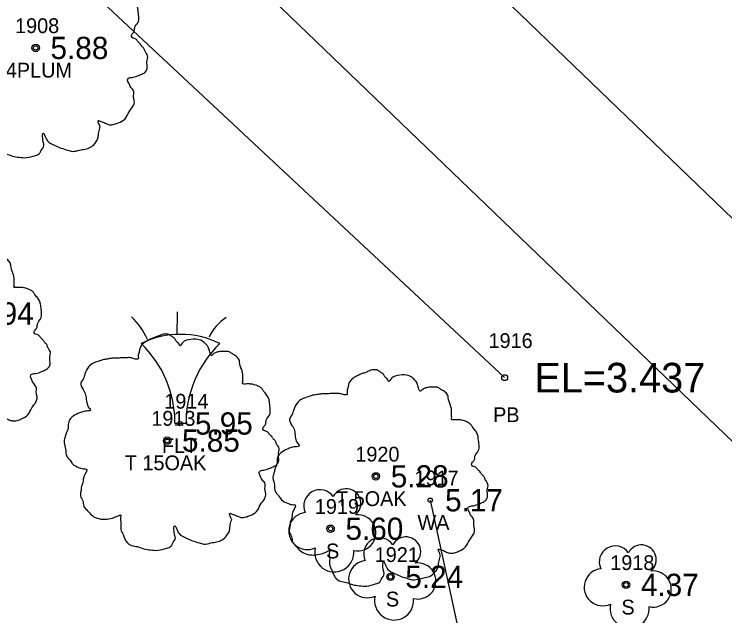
# Model space of a CAD drawing. Extents: x 2608598 to 2610682, y 641451 to 643526.
# Drawn here: x 2609231.28 to 2609279.19, y 642898.29 to 642938.88 of the extents above; entities that cross this region are included whole.
import ezdxf

# ---------------------------------------------------------------- set-up
doc = ezdxf.new("R2010")
doc.units = 0
for name, color, linetype in [('RD_EX_BldgApp', 7, 'Continuous'), ('RD_EX_BldgApp_txCode', 7, 'Continuous'), ('RD_EX_DR_Pipe', 7, 'Continuous'), ('RD_EX_DR_Pipe_txCode', 7, 'Continuous'), ('RD_EX_Misc_txCode', 7, 'Continuous'), ('RD_EX_Road', 7, 'Continuous'), ('RD_EX_TX_BldgApp_ELEV', 7, 'Continuous'), ('RD_EX_TX_Misc_ELEV', 7, 'Continuous'), ('RD_EX_TX_VEG_ELEV', 7, 'Continuous'), ('RD_EX_VEG', 7, 'Continuous'), ('RD_EX_VEG_txCode', 7, 'Continuous'), ('RD_HC_Cl', 7, 'Continuous'), ('RD_SMD_Locator', 7, 'Continuous'), ('RD_TX_Pipe_ElevEX', 7, 'Continuous')]:
    doc.layers.add(name, color=color, linetype=linetype)

msp = doc.modelspace()

# ---------------------------------------------------------------- linework, layer by layer
at = {"layer": 'RD_EX_BldgApp'}
msp.add_line((2609242.116, 642911.284), (2609242.866, 642911.284), dxfattribs=at)
msp.add_lwpolyline([(2609259.329, 642906.089), (2609262.471, 642891.581), (2609238.117, 642881.572), (2609215.937, 642874.826), (2609203.404, 642873.665)], dxfattribs=at)
for centre, radius, start, end in [((2609204.409, 642918.622), 37.876, 358.0671, 0.2715), ((2609235.798, 642914.927), 4.895, 24.3279, 46.2665), ((2609247.379, 642915.678), 3.283, 123.2906, 154.4886), ((2609242.491, 642911.284), 5.997, 63.7794, 116.2206), ((2609234.616, 642911.284), 7.5, 0, 45.8366), ((2609250.366, 642911.284), 7.5, 134.1634, 180)]:
    msp.add_arc(centre, radius, start, end, dxfattribs=at)
at = {"layer": 'RD_EX_DR_Pipe'}
msp.add_lwpolyline([(2609067.894, 643101.844), (2609174.278, 642998.399), (2609174.637, 642998.15), (2609264.347, 642914.358)], dxfattribs=at)
at = {"layer": 'RD_EX_Road'}
msp.add_lwpolyline([(2608806.889, 643364.989), (2608810.184, 643361.1), (2608820.754, 643351.249), (2608881.81, 643292.235), (2608917.833, 643257.495), (2608933.208, 643242.709), (2608954.068, 643222.833), (2609026.064, 643154.189), (2609039.601, 643139.963), (2609073.879, 643106.954), (2609100.48, 643081.888), (2609124.194, 643058.866), (2609171.612, 643013.711), (2609183.195, 643002.284), (2609197.913, 642988.365), (2609247.586, 642940.954), (2609328.02, 642863.599), (2609402.609, 642790.299), (2609474.235, 642720.69), (2609483.838, 642711.579), (2609495.782, 642699.917), (2609509.808, 642686.45)], dxfattribs=at)
at = {"layer": 'RD_EX_VEG'}
for centre, radius in [((2609232.725, 642936.603), 0.25), ((2609232.712, 642936.585), 0.0001), ((2609241.588, 642910.111), 0.25), ((2609241.575, 642910.092), 0.0001), ((2609255.666, 642907.698), 0.25), ((2609255.653, 642907.679), 0.0001), ((2609252.612, 642904.167), 0.25), ((2609256.649, 642900.919), 0.25), ((2609272.529, 642900.378), 0.25)]:
    msp.add_circle(centre, radius, dxfattribs=at)
for centre, radius, start, end in [((2609251.891, 642905.714), 1.084, 34.9763, 204.756), ((2609253.657, 642905.869), 0.995, 308.7626, 152.0467), ((2609251.048, 642904.011), 1.257, 96.4518, 294.734), ((2609254.452, 642903.887), 1.218, 256.5667, 98.1046), ((2609255.928, 642902.466), 1.084, 34.9763, 204.756), ((2609257.695, 642902.621), 0.995, 308.7626, 152.0467), ((2609252.858, 642902.57), 1.318, 166.8827, 5.7589), ((2609271.808, 642901.925), 1.084, 34.9763, 204.756), ((2609273.574, 642902.08), 0.995, 308.7626, 152.0467), ((2609255.086, 642900.763), 1.257, 96.4518, 294.734), ((2609258.489, 642900.64), 1.218, 256.5667, 98.1046), ((2609270.965, 642900.222), 1.257, 96.4518, 294.734), ((2609274.368, 642900.099), 1.218, 256.5667, 98.1046), ((2609256.895, 642899.323), 1.318, 166.8827, 5.7589), ((2609272.774, 642898.782), 1.318, 166.8827, 5.7589)]:
    msp.add_arc(centre, radius, start, end, dxfattribs=at)
for points in [[(2609232.857, 642943.771), (2609232.557, 642943.796), (2609232.232, 642943.696), (2609231.982, 642943.596), (2609231.757, 642943.521), (2609231.532, 642943.421), (2609231.232, 642943.246), (2609231.008, 642943.046), (2609230.883, 642942.796), (2609230.833, 642942.571), (2609230.783, 642942.296), (2609230.783, 642942.121), (2609230.658, 642942.096), (2609230.508, 642942.121), (2609230.258, 642942.196), (2609230.008, 642942.196), (2609229.758, 642942.196), (2609229.408, 642942.171), (2609229.058, 642942.171), (2609228.784, 642942.121), (2609228.459, 642942.071), (2609228.084, 642941.946), (2609227.734, 642941.821), (2609227.434, 642941.572), (2609227.184, 642941.097), (2609227.059, 642940.747), (2609226.909, 642940.497), (2609227.059, 642940.047), (2609227.234, 642939.697), (2609227.259, 642939.497), (2609227.334, 642939.073), (2609227.434, 642938.848), (2609227.559, 642938.648), (2609227.484, 642938.623), (2609227.109, 642938.573), (2609226.809, 642938.473), (2609226.385, 642938.248), (2609226.16, 642938.023), (2609226.06, 642937.698), (2609226.035, 642937.348), (2609225.935, 642937.149), (2609225.86, 642936.874), (2609225.835, 642936.799), (2609225.785, 642936.474), (2609225.885, 642936.024), (2609225.91, 642935.674), (2609226.035, 642935.449), (2609226.185, 642935.274), (2609226.36, 642935.024), (2609226.759, 642934.8), (2609227.084, 642934.7), (2609227.284, 642934.675), (2609227.109, 642934.175), (2609227.059, 642933.825), (2609226.934, 642933.425), (2609226.934, 642933.35), (2609226.884, 642932.875), (2609227.034, 642932.55), (2609227.109, 642932.176), (2609227.284, 642931.951), (2609227.559, 642931.651), (2609227.884, 642931.426), (2609228.384, 642931.301), (2609228.784, 642931.326), (2609229.358, 642931.501), (2609229.608, 642931.576), (2609229.583, 642931.401), (2609229.608, 642931.026), (2609229.608, 642930.601), (2609229.758, 642930.277), (2609229.858, 642930.002), (2609230.008, 642929.752), (2609230.333, 642929.527), (2609230.733, 642929.452), (2609231.157, 642929.302), (2609231.607, 642929.227), (2609232.107, 642929.202), (2609232.707, 642929.352), (2609232.982, 642929.477), (2609233.082, 642929.652), (2609233.282, 642930.027), (2609233.232, 642930.252), (2609233.257, 642930.851), (2609233.356, 642930.676), (2609233.531, 642930.326), (2609234.031, 642930.027), (2609234.431, 642929.852), (2609234.906, 642929.702), (2609235.206, 642929.627), (2609235.68, 642929.702), (2609236.055, 642929.777), (2609236.43, 642929.902), (2609236.73, 642930.177), (2609236.905, 642930.451), (2609236.955, 642930.726), (2609237.03, 642931.101), (2609237.08, 642931.276)], [(2609237.08, 642931.276), (2609237.005, 642931.451), (2609236.955, 642931.701), (2609237.03, 642931.676), (2609237.205, 642931.626), (2609237.48, 642931.501), (2609237.705, 642931.426), (2609238.029, 642931.451), (2609238.304, 642931.551), (2609238.754, 642931.826), (2609239.029, 642932.301), (2609239.304, 642932.7), (2609239.379, 642933.025), (2609239.329, 642933.25), (2609239.304, 642933.75), (2609239.104, 642934), (2609239.054, 642934.125), (2609238.954, 642934.525), (2609239.029, 642934.575), (2609239.304, 642934.625), (2609239.679, 642934.75), (2609239.954, 642934.874), (2609240.179, 642935.049), (2609240.253, 642935.274), (2609240.229, 642935.674), (2609240.278, 642936.074), (2609240.204, 642936.224), (2609240.104, 642936.374), (2609240.029, 642936.574), (2609239.879, 642936.724), (2609239.779, 642936.874), (2609239.679, 642936.974), (2609239.554, 642937.124), (2609239.379, 642937.248), (2609239.229, 642937.298), (2609239.179, 642937.448), (2609239.329, 642937.648), (2609239.379, 642937.748), (2609239.404, 642937.973), (2609239.629, 642938.323), (2609239.679, 642938.723), (2609239.629, 642939.148), (2609239.579, 642939.423), (2609239.429, 642939.697), (2609239.229, 642939.947), (2609239.104, 642940.122), (2609238.929, 642940.247), (2609238.604, 642940.372), (2609238.354, 642940.422), (2609238.004, 642940.422), (2609237.805, 642940.472), (2609237.83, 642940.522), (2609237.83, 642940.672), (2609237.83, 642940.947), (2609237.755, 642941.397), (2609237.605, 642941.896), (2609237.605, 642941.921), (2609237.505, 642942.171), (2609237.28, 642942.371), (2609237.105, 642942.471), (2609236.905, 642942.596), (2609236.655, 642942.621), (2609236.355, 642942.621), (2609236.08, 642942.571), (2609235.88, 642942.471), (2609235.705, 642942.346), (2609235.63, 642942.496), (2609235.531, 642942.796), (2609235.481, 642942.946), (2609235.331, 642943.121), (2609235.106, 642943.321), (2609234.656, 642943.446), (2609234.031, 642943.371), (2609233.731, 642943.171), (2609233.581, 642942.996), (2609233.531, 642943.121), (2609233.331, 642943.321), (2609233.232, 642943.496), (2609233.057, 642943.621), (2609232.907, 642943.721), (2609232.807, 642943.771)], [(2609230.524, 642911.295), (2609230.449, 642911.47), (2609230.399, 642911.72), (2609230.474, 642911.695), (2609230.649, 642911.645), (2609230.924, 642911.52), (2609231.149, 642911.445), (2609231.473, 642911.47), (2609231.748, 642911.57), (2609232.198, 642911.845), (2609232.473, 642912.32), (2609232.748, 642912.72), (2609232.823, 642913.045), (2609232.773, 642913.27), (2609232.748, 642913.769), (2609232.548, 642914.019), (2609232.498, 642914.144), (2609232.398, 642914.544), (2609232.473, 642914.594), (2609232.748, 642914.644), (2609233.123, 642914.769), (2609233.398, 642914.894), (2609233.622, 642915.069), (2609233.697, 642915.294), (2609233.672, 642915.693), (2609233.722, 642916.093), (2609233.647, 642916.243), (2609233.547, 642916.393), (2609233.472, 642916.593), (2609233.323, 642916.743), (2609233.223, 642916.893), (2609233.123, 642916.993), (2609232.998, 642917.143), (2609232.823, 642917.268), (2609232.673, 642917.318), (2609232.623, 642917.468), (2609232.773, 642917.668), (2609232.823, 642917.768), (2609232.848, 642917.992), (2609233.073, 642918.342), (2609233.123, 642918.742), (2609233.073, 642919.167), (2609233.023, 642919.442), (2609232.873, 642919.717), (2609232.673, 642919.967), (2609232.548, 642920.142), (2609232.373, 642920.266), (2609232.048, 642920.391), (2609231.798, 642920.441), (2609231.448, 642920.441), (2609231.248, 642920.491), (2609231.273, 642920.541), (2609231.273, 642920.691), (2609231.273, 642920.966), (2609231.198, 642921.416), (2609231.049, 642921.916), (2609231.049, 642921.941), (2609230.949, 642922.191), (2609230.724, 642922.391), (2609230.549, 642922.49), (2609230.349, 642922.615), (2609230.099, 642922.64), (2609229.799, 642922.64), (2609229.524, 642922.59), (2609229.324, 642922.49), (2609229.149, 642922.366), (2609229.074, 642922.515), (2609228.974, 642922.815), (2609228.924, 642922.965), (2609228.775, 642923.14), (2609228.55, 642923.34), (2609228.1, 642923.465), (2609227.475, 642923.39), (2609227.175, 642923.19), (2609227.025, 642923.015), (2609226.975, 642923.14), (2609226.775, 642923.34), (2609226.675, 642923.515), (2609226.501, 642923.64), (2609226.351, 642923.74), (2609226.251, 642923.79)], [(2609241.72, 642917.278), (2609241.42, 642917.303), (2609241.095, 642917.203), (2609240.845, 642917.103), (2609240.62, 642917.028), (2609240.396, 642916.928), (2609240.096, 642916.753), (2609239.871, 642916.553), (2609239.746, 642916.303), (2609239.696, 642916.079), (2609239.646, 642915.804), (2609239.646, 642915.629), (2609239.521, 642915.604), (2609239.371, 642915.629), (2609239.121, 642915.704), (2609238.871, 642915.704), (2609238.621, 642915.704), (2609238.271, 642915.679), (2609237.922, 642915.679), (2609237.647, 642915.629), (2609237.322, 642915.579), (2609236.947, 642915.454), (2609236.597, 642915.329), (2609236.297, 642915.079), (2609236.047, 642914.604), (2609235.922, 642914.254), (2609235.773, 642914.004), (2609235.922, 642913.555), (2609236.097, 642913.205), (2609236.122, 642913.005), (2609236.197, 642912.58), (2609236.297, 642912.355), (2609236.422, 642912.155), (2609236.347, 642912.13), (2609235.972, 642912.08), (2609235.673, 642911.98), (2609235.248, 642911.755), (2609235.023, 642911.531), (2609234.923, 642911.206), (2609234.898, 642910.856), (2609234.798, 642910.656), (2609234.723, 642910.381), (2609234.698, 642910.306), (2609234.648, 642909.981), (2609234.748, 642909.531), (2609234.773, 642909.182), (2609234.898, 642908.957), (2609235.048, 642908.782), (2609235.223, 642908.532), (2609235.623, 642908.307), (2609235.947, 642908.207), (2609236.147, 642908.182), (2609235.972, 642907.682), (2609235.922, 642907.332), (2609235.798, 642906.933), (2609235.798, 642906.858), (2609235.748, 642906.383), (2609235.897, 642906.058), (2609235.972, 642905.683), (2609236.147, 642905.458), (2609236.422, 642905.158), (2609236.747, 642904.933), (2609237.247, 642904.808), (2609237.647, 642904.833), (2609238.222, 642905.008), (2609238.471, 642905.083), (2609238.446, 642904.908), (2609238.471, 642904.534), (2609238.471, 642904.109), (2609238.621, 642903.784), (2609238.721, 642903.509), (2609238.871, 642903.259), (2609239.196, 642903.034), (2609239.596, 642902.959), (2609240.021, 642902.809), (2609240.471, 642902.734), (2609240.97, 642902.709), (2609241.57, 642902.859), (2609241.845, 642902.984), (2609241.945, 642903.159), (2609242.145, 642903.534), (2609242.095, 642903.759), (2609242.12, 642904.359), (2609242.22, 642904.184), (2609242.395, 642903.834), (2609242.894, 642903.534), (2609243.294, 642903.359), (2609243.769, 642903.209), (2609244.069, 642903.134), (2609244.544, 642903.209), (2609244.919, 642903.284), (2609245.293, 642903.409), (2609245.593, 642903.684), (2609245.768, 642903.959), (2609245.818, 642904.234), (2609245.893, 642904.609), (2609245.943, 642904.783)], [(2609245.943, 642904.783), (2609245.868, 642904.958), (2609245.818, 642905.208), (2609245.893, 642905.183), (2609246.068, 642905.133), (2609246.343, 642905.008), (2609246.568, 642904.933), (2609246.893, 642904.958), (2609247.168, 642905.058), (2609247.617, 642905.333), (2609247.892, 642905.808), (2609248.167, 642906.208), (2609248.242, 642906.533), (2609248.192, 642906.758), (2609248.167, 642907.257), (2609247.967, 642907.507), (2609247.917, 642907.632), (2609247.817, 642908.032), (2609247.892, 642908.082), (2609248.167, 642908.132), (2609248.542, 642908.257), (2609248.817, 642908.382), (2609249.042, 642908.557), (2609249.117, 642908.782), (2609249.092, 642909.182), (2609249.142, 642909.581), (2609249.067, 642909.731), (2609248.967, 642909.881), (2609248.892, 642910.081), (2609248.742, 642910.231), (2609248.642, 642910.381), (2609248.542, 642910.481), (2609248.417, 642910.631), (2609248.242, 642910.756), (2609248.092, 642910.806), (2609248.042, 642910.956), (2609248.192, 642911.156), (2609248.242, 642911.256), (2609248.267, 642911.481), (2609248.492, 642911.83), (2609248.542, 642912.23), (2609248.492, 642912.655), (2609248.442, 642912.93), (2609248.292, 642913.205), (2609248.092, 642913.455), (2609247.967, 642913.63), (2609247.792, 642913.755), (2609247.467, 642913.88), (2609247.218, 642913.929), (2609246.868, 642913.929), (2609246.668, 642913.979), (2609246.693, 642914.029), (2609246.693, 642914.179), (2609246.693, 642914.454), (2609246.618, 642914.904), (2609246.468, 642915.404), (2609246.468, 642915.429), (2609246.368, 642915.679), (2609246.143, 642915.879), (2609245.968, 642915.979), (2609245.768, 642916.104), (2609245.518, 642916.129), (2609245.218, 642916.129), (2609244.944, 642916.079), (2609244.744, 642915.979), (2609244.569, 642915.854), (2609244.494, 642916.004), (2609244.394, 642916.303), (2609244.344, 642916.453), (2609244.194, 642916.628), (2609243.969, 642916.828), (2609243.519, 642916.953), (2609242.894, 642916.878), (2609242.595, 642916.678), (2609242.445, 642916.503), (2609242.395, 642916.628), (2609242.195, 642916.828), (2609242.095, 642917.003), (2609241.92, 642917.128), (2609241.77, 642917.228), (2609241.67, 642917.278)], [(2609255.797, 642914.865), (2609255.498, 642914.89), (2609255.173, 642914.79), (2609254.923, 642914.69), (2609254.698, 642914.615), (2609254.473, 642914.515), (2609254.173, 642914.34), (2609253.948, 642914.14), (2609253.823, 642913.89), (2609253.773, 642913.665), (2609253.723, 642913.39), (2609253.723, 642913.215), (2609253.598, 642913.19), (2609253.448, 642913.215), (2609253.199, 642913.29), (2609252.949, 642913.29), (2609252.699, 642913.29), (2609252.349, 642913.265), (2609251.999, 642913.265), (2609251.724, 642913.215), (2609251.399, 642913.166), (2609251.025, 642913.041), (2609250.675, 642912.916), (2609250.375, 642912.666), (2609250.125, 642912.191), (2609250, 642911.841), (2609249.85, 642911.591), (2609250, 642911.141), (2609250.175, 642910.792), (2609250.2, 642910.592), (2609250.275, 642910.167), (2609250.375, 642909.942), (2609250.5, 642909.742), (2609250.425, 642909.717), (2609250.05, 642909.667), (2609249.75, 642909.567), (2609249.325, 642909.342), (2609249.1, 642909.117), (2609249, 642908.792), (2609248.975, 642908.443), (2609248.876, 642908.243), (2609248.801, 642907.968), (2609248.776, 642907.893), (2609248.726, 642907.568), (2609248.826, 642907.118), (2609248.851, 642906.768), (2609248.975, 642906.543), (2609249.125, 642906.369), (2609249.3, 642906.119), (2609249.7, 642905.894), (2609250.025, 642905.794), (2609250.225, 642905.769), (2609250.05, 642905.269), (2609250, 642904.919), (2609249.875, 642904.519), (2609249.875, 642904.444), (2609249.825, 642903.97), (2609249.975, 642903.645), (2609250.05, 642903.27), (2609250.225, 642903.045), (2609250.5, 642902.745), (2609250.825, 642902.52), (2609251.324, 642902.395), (2609251.724, 642902.42), (2609252.299, 642902.595), (2609252.549, 642902.67), (2609252.524, 642902.495), (2609252.549, 642902.12), (2609252.549, 642901.696), (2609252.699, 642901.371), (2609252.799, 642901.096), (2609252.949, 642900.846), (2609253.274, 642900.621), (2609253.673, 642900.546), (2609254.098, 642900.396), (2609254.548, 642900.321), (2609255.048, 642900.296), (2609255.648, 642900.446), (2609255.922, 642900.571), (2609256.022, 642900.746), (2609256.222, 642901.121), (2609256.172, 642901.346), (2609256.197, 642901.945), (2609256.297, 642901.77), (2609256.472, 642901.421), (2609256.972, 642901.121), (2609257.372, 642900.946), (2609257.847, 642900.796), (2609258.146, 642900.721), (2609258.621, 642900.796), (2609258.996, 642900.871), (2609259.371, 642900.996), (2609259.671, 642901.271), (2609259.846, 642901.546), (2609259.896, 642901.82), (2609259.971, 642902.195), (2609260.021, 642902.37)], [(2609260.021, 642902.37), (2609259.946, 642902.545), (2609259.896, 642902.795), (2609259.971, 642902.77), (2609260.146, 642902.72), (2609260.42, 642902.595), (2609260.645, 642902.52), (2609260.97, 642902.545), (2609261.245, 642902.645), (2609261.695, 642902.92), (2609261.97, 642903.395), (2609262.245, 642903.795), (2609262.32, 642904.119), (2609262.27, 642904.344), (2609262.245, 642904.844), (2609262.045, 642905.094), (2609261.995, 642905.219), (2609261.895, 642905.619), (2609261.97, 642905.669), (2609262.245, 642905.719), (2609262.619, 642905.844), (2609262.894, 642905.969), (2609263.119, 642906.144), (2609263.194, 642906.369), (2609263.169, 642906.768), (2609263.219, 642907.168), (2609263.144, 642907.318), (2609263.044, 642907.468), (2609262.969, 642907.668), (2609262.819, 642907.818), (2609262.719, 642907.968), (2609262.619, 642908.068), (2609262.495, 642908.218), (2609262.32, 642908.343), (2609262.17, 642908.393), (2609262.12, 642908.543), (2609262.27, 642908.742), (2609262.32, 642908.842), (2609262.345, 642909.067), (2609262.57, 642909.417), (2609262.619, 642909.817), (2609262.57, 642910.242), (2609262.52, 642910.517), (2609262.37, 642910.792), (2609262.17, 642911.041), (2609262.045, 642911.216), (2609261.87, 642911.341), (2609261.545, 642911.466), (2609261.295, 642911.516), (2609260.945, 642911.516), (2609260.745, 642911.566), (2609260.77, 642911.616), (2609260.77, 642911.766), (2609260.77, 642912.041), (2609260.695, 642912.491), (2609260.545, 642912.991), (2609260.545, 642913.016), (2609260.445, 642913.265), (2609260.221, 642913.465), (2609260.046, 642913.565), (2609259.846, 642913.69), (2609259.596, 642913.715), (2609259.296, 642913.715), (2609259.021, 642913.665), (2609258.821, 642913.565), (2609258.646, 642913.44), (2609258.571, 642913.59), (2609258.471, 642913.89), (2609258.421, 642914.04), (2609258.271, 642914.215), (2609258.047, 642914.415), (2609257.597, 642914.54), (2609256.972, 642914.465), (2609256.672, 642914.265), (2609256.522, 642914.09), (2609256.472, 642914.215), (2609256.272, 642914.415), (2609256.172, 642914.59), (2609255.997, 642914.715), (2609255.847, 642914.815), (2609255.747, 642914.865)]]:
    msp.add_spline(points, degree=3, dxfattribs=at)
at = {"layer": 'RD_HC_Cl'}
msp.add_line((2608814.812, 643373.733), (2610092.394, 642140.787), dxfattribs=at)
at = {"layer": 'RD_SMD_Locator'}
for centre, radius in [((2609232.725, 642936.603), 0.15), ((2609264.347, 642914.358), 0.2), ((2609242.463, 642911.266), 0.15), ((2609241.588, 642910.111), 0.15), ((2609255.666, 642907.698), 0.15), ((2609259.329, 642906.089), 0.15), ((2609252.612, 642904.167), 0.15), ((2609256.649, 642900.919), 0.15), ((2609272.529, 642900.378), 0.15)]:
    msp.add_circle(centre, radius, dxfattribs=at)

# ---------------------------------------------------------------- texts
at = {"layer": 'RD_EX_BldgApp_txCode'}
for s, p in [('1914', (2609241.4, 642912.266)), ('FLT', (2609241.243, 642909.266))]:
    msp.add_text(s, height=1, dxfattribs=at).set_placement(p)
at = {"layer": 'RD_EX_DR_Pipe_txCode'}
for s, p in [('1916', (2609263.26, 642916.358)), ('PB', (2609263.567, 642911.358))]:
    msp.add_text(s, height=1, dxfattribs=at).set_placement(p)
at = {"layer": 'RD_EX_Misc_txCode'}
for s, p in [('1917', (2609258.266, 642907.089)), ('WA', (2609258.471, 642904.089))]:
    msp.add_text(s, height=1, dxfattribs=at).set_placement(p)
at = {"layer": 'RD_EX_TX_BldgApp_ELEV'}
for s, p in [('6.94', (2609228.691, 642917.936)), ('5.95', (2609243.463, 642910.516))]:
    msp.add_text(s, height=1.5, dxfattribs=at).set_placement(p)
at = {"layer": 'RD_EX_TX_Misc_ELEV'}
msp.add_text('5.17', height=1.5, dxfattribs=at).set_placement((2609260.329, 642905.339))
at = {"layer": 'RD_EX_TX_VEG_ELEV'}
for s, p in [('5.88', (2609233.725, 642935.853)), ('5.85', (2609242.588, 642909.361)), ('5.28', (2609256.666, 642906.948)), ('5.60', (2609253.612, 642903.417)), ('5.24', (2609257.649, 642900.169)), ('4.37', (2609273.529, 642899.628))]:
    msp.add_text(s, height=1.5, dxfattribs=at).set_placement(p)
at = {"layer": 'RD_EX_VEG_txCode'}
for s, p in [('1908', (2609231.339, 642937.603)), ('T 4PLUM', (2609229.528, 642934.603)), ('1913', (2609240.525, 642911.111)), ('1920', (2609254.28, 642908.698)), ('T 15OAK', (2609238.738, 642908.111)), ('T 5OAK', (2609252.98, 642905.698)), ('1919', (2609251.549, 642905.167)), ('S', (2609252.305, 642902.167)), ('1921', (2609255.587, 642901.919)), ('1918', (2609271.466, 642901.378)), ('S', (2609256.342, 642898.919)), ('S', (2609272.222, 642898.378))]:
    msp.add_text(s, height=1, dxfattribs=at).set_placement(p)
at = {"layer": 'RD_TX_Pipe_ElevEX'}
msp.add_text('EL=3.437', height=2, dxfattribs=at).set_placement((2609266.347, 642913.358))

doc.saveas('drawing.dxf')
